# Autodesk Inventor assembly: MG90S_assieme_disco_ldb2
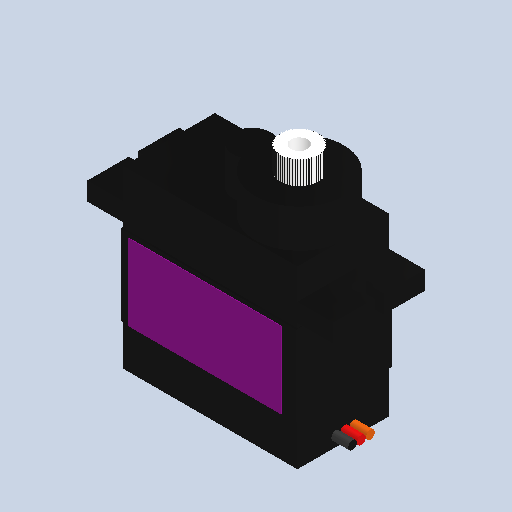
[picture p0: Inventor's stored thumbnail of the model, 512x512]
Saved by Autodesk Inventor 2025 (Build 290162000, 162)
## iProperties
Created: 2021-06
Part Number: MG90S_assieme_disco_ldb2
Document SubType Name: Assembly
Designer: Ryzen5700u
Author: Ryzen5700u
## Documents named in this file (3)
- C:\Users\Ryzen5700u\Desktop\scara\Assieme_scara_03\MG90S_assieme_disco_ldb2.iam
- C:\Users\Ryzen5700u\Desktop\scara\Assieme_scara_03\MG90_ldb.ipt
- C:\Users\Ryzen5700u\Desktop\scara\Assieme_scara_03\scritta_MG90s.ipt
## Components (3 placed, 2 different names)
1. MG90_ldb:1
2. scritta_MG90s:1
3. scritta_MG90s:2
